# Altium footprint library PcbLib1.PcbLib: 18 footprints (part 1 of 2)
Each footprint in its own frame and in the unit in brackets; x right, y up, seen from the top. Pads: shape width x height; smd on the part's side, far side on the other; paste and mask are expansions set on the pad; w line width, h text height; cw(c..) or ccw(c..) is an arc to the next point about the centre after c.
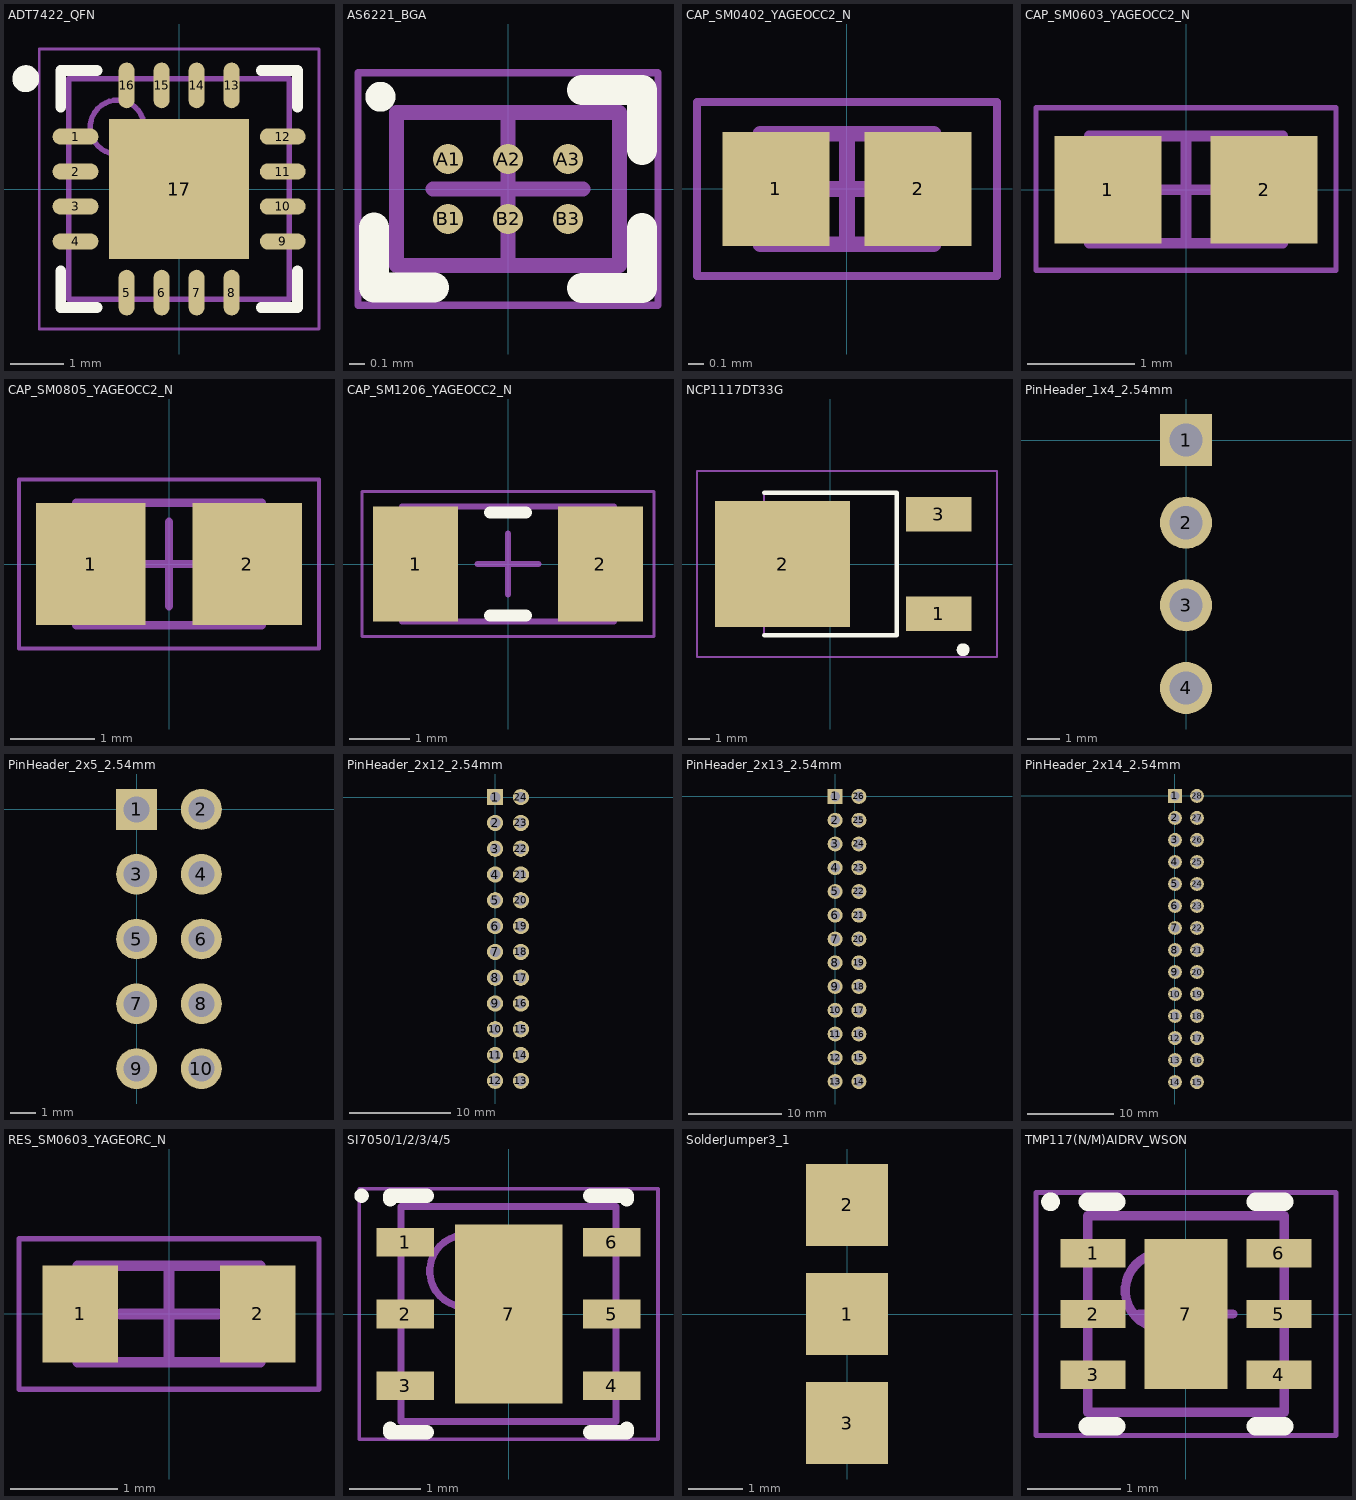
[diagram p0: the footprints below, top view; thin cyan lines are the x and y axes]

## ADT7422_QFN [mm] "QFN, 16-Leads, Body 4,00x4,00mm, Pitch 0,65mm, Thermal Pad 2,60x2,60mm, IPC Medium Density"
height 0.8
pads (17):
  oval 0.85x0.3 smd: 1(-1.925,0.975) 2(-1.925,0.325) 3(-1.925,-0.325) 4(-1.925,-0.975) 9(1.925,-0.975) 10(1.925,-0.325) 11(1.925,0.325) 12(1.925,0.975)
  oval 0.3x0.85 smd: 5(-0.975,-1.925) 6(-0.325,-1.925) 7(0.325,-1.925) 8(0.975,-1.925) 13(0.975,1.925) 14(0.325,1.925) 15(-0.325,1.925) 16(-0.975,1.925)
  rect 2.6x2.6 smd: 17(0,0)
Top Overlay:
  circle w0.25: c-2.85,2.05 r0.125
  lines w0.2: -2.2,-1.525 -2.2,-2.2 -1.525,-2.2 ; -2.2,1.525 -2.2,2.2 -1.525,2.2 ; 1.525,-2.2 2.2,-2.2 2.2,-1.525 ; 1.525,2.2 2.2,2.2 2.2,1.525
Top Courtyard:
  lines w0.05: -2.6,-2.6 -2.6,2.6 2.6,2.6 2.6,-2.6 -2.6,-2.6
  lines w0.1: -0.5,0 0.5,0 ; 0,-0.5 0,0.5
Mechanical 13:
  circle w0.1: c-1.15,1.15 r0.5
  lines w0.1: -2.05,-2.05 -2.05,2.05 2.05,2.05 2.05,-2.05 -2.05,-2.05
3D body: height 0.8, standoff 0.01, extent -2.05,-2.05 2.05,2.05

## AS6221_BGA [mm] "BGA, 6-Leads, Body 1,02x1,50mmx0,53mm, Pitch 0,40mm"
height 0.53
pads (6):
  round 0.2 smd: A1(-0.4,0.2) A2(0,0.2) A3(0.4,0.2) B1(-0.4,-0.2) B2(0,-0.2) B3(0.4,-0.2)
Top Overlay:
  circle w0.1: c-0.85,0.615 r0.05
  lines w0.2: -0.893,-0.256 -0.893,-0.656 -0.493,-0.656 ; 0.494,-0.66 0.894,-0.66 0.894,-0.26 ; 0.494,0.661 0.894,0.661 0.894,0.261
Top Courtyard:
  lines w0.05: -1,-0.775 -1,0.775 1,0.775 1,-0.775 -1,-0.775
  lines w0.1: -0.5,0 0.5,0 ; 0,-0.5 0,0.5
Mechanical 13:
  lines w0.1: -0.745,-0.51 -0.745,0.51 0.745,0.51 0.745,-0.51 -0.745,-0.51
3D body: height 0.55, standoff 0.18, extent -0.745,-0.51 0.745,0.51

## CAP_SM0402_YAGEOCC2_N [mm] "Capacitor, Yageo CC Class2, SM0402, IPC Medium Density"
height 0.9
pads (2):
  rect 0.68x0.72 smd: 1(-0.45,0) 2(0.45,0)
Mechanical 13:
  lines w0.1: -0.55,-0.35 -0.55,0.35 0.55,0.35 0.55,-0.35 -0.55,-0.35
Mechanical 15:
  lines w0.05: -0.95,-0.55 -0.95,0.55 0.95,0.55 0.95,-0.55 -0.95,-0.55
  lines w0.1: -0.35,0 0.35,0 ; 0,-0.35 0,0.35
3D body: height 0.6, standoff 0, extent -0.3,-0.35 0.3,0.35
3D body: height 0.6, standoff 0, extent -0.55,-0.35 -0.3,0.35
3D body: height 0.6, standoff 0, extent 0.3,-0.35 0.55,0.35

## CAP_SM0603_YAGEOCC2_N [mm] "Capacitor, Yageo CC Class2, SM0603, IPC Medium Density"
height 0.9
pads (2):
  rect 1x1 smd: 1(-0.727,0) 2(0.727,0)
Mechanical 13:
  lines w0.1: -0.9,-0.5 0.9,-0.5 0.9,0.5 -0.9,0.5 -0.9,-0.5
Mechanical 15:
  lines w0.05: -1.397,-0.75 1.397,-0.75 1.397,0.762 -1.397,0.762 -1.397,-0.75
  lines w0.1: -0.5,0 0.5,0 ; 0,-0.5 0,0.5
3D body: height 0.9, standoff 0, extent 0.5,-0.5 0.9,0.5
3D body: height 0.9, standoff 0, extent -0.9,-0.5 -0.5,0.5
3D body: height 0.9, standoff 0, extent -0.5,-0.5 0.5,0.5

## CAP_SM0805_YAGEOCC2_N [mm] "Capacitor, Yageo CC Class2, SM0805, IPC Medium Density"
height 1.45
pads (2):
  rect 1.3x1.45 smd: 1(-0.927,0) 2(0.927,0)
Mechanical 13:
  lines w0.1: -1.1,-0.725 -1.1,0.725 1.1,0.725 1.1,-0.725 -1.1,-0.725
Mechanical 15:
  lines w0.05: -1.778,-1 -1.778,1 1.778,1 1.778,-1 -1.778,-1
  lines w0.1: -0.5,0 0.5,0 ; 0,-0.5 0,0.5
3D body: height 1.45, standoff 0, extent -0.6,-0.725 0.6,0.725
3D body: height 1.45, standoff 0, extent -1.1,-0.725 -0.6,0.725
3D body: height 1.45, standoff 0, extent 0.6,-0.725 1.1,0.725

## CAP_SM1206_YAGEOCC2_N [mm] "Capacitor, Yageo CC Class2, SM1206, IPC Medium Density"
height 1.8
pads (2):
  rect 1.4x1.9 smd: 1(-1.527,0) 2(1.527,0)
Top Overlay:
  lines w0.2: -0.3,-0.85 0.3,-0.85 ; -0.3,0.85 0.3,0.85
Mechanical 13:
  lines w0.1: -1.75,-0.95 -1.75,0.95 1.75,0.95 1.75,-0.95 -1.75,-0.95
Mechanical 15:
  lines w0.05: -2.413,-1.2 -2.413,1.2 2.413,1.2 2.413,-1.2 -2.413,-1.2
  lines w0.1: -0.5,0 0.5,0 ; 0,-0.5 0,0.5
3D body: height 1.8, standoff 0, extent -1.25,-0.95 1.25,0.95
3D body: height 1.8, standoff 0, extent -1.75,-0.95 -1.25,0.95
3D body: height 1.8, standoff 0, extent 1.25,-0.95 1.75,0.95

## NCP1117DT33G [mm]
pads (3):
  rect 3x1.6 smd: 1(4.982,-2.285) 3(4.982,2.285)
  rect 6.2x5.8 smd: 2(-2.198,0)
Top Overlay:
  lines w0.2: -3.047,-3.27 3.048,-3.27 3.048,3.27 -3.047,3.27 ; 6.096,-3.741 ccw(c6.096,-3.937) 6.146,-3.747 ; 6.084,-3.936 cw(c6.134,-3.936) 6.184,-3.936 cw(c6.134,-3.936) 6.084,-3.936
Mechanical 15:
  lines w0.1: -3.047,-3.27 -3.047,3.27 3.048,3.27 3.048,-3.27 -3.047,-3.27
Mechanical 20:
  lines w0.1: -6.128,-4.27 -6.128,4.27 7.652,4.27 7.652,-4.27 -6.128,-4.27
3D body "NCP1117DT33G.stp": height 2.69, standoff -0.02, extent -4.678,-3.335 5.74,3.395

## PinHeader_1x4_2.54mm [mm]
pads (4):
  rect 1.6x1.6 hole 1.02: 1(0,0)
  round 1.6 hole 1.02: 2(0,-2.54) 3(0,-5.08) 4(0,-7.62)

## PinHeader_2x5_2.54mm [mm]
pads (10):
  rect 1.6x1.6 hole 1.02: 1(0,0)
  round 1.6 hole 1.02: 2(2.54,0) 3(0,-2.54) 4(2.54,-2.54) 5(0,-5.08) 6(2.54,-5.08) 7(0,-7.62) 8(2.54,-7.62) 9(0,-10.16) 10(2.54,-10.16)

## PinHeader_2x12_2.54mm [mm]
pads (24):
  rect 1.6x1.6 hole 1.02: 1(0,0)
  round 1.6 hole 1.02: 2(0,-2.54) 3(0,-5.08) 4(0,-7.62) 5(0,-10.16) 6(0,-12.7) 7(0,-15.24) 8(0,-17.78) 9(0,-20.32) 10(0,-22.86) 11(0,-25.4) 12(0,-27.94) 13(2.54,-27.94) 14(2.54,-25.4) 15(2.54,-22.86) 16(2.54,-20.32) 17(2.54,-17.78) 18(2.54,-15.24) 19(2.54,-12.7) 20(2.54,-10.16) 21(2.54,-7.62) 22(2.54,-5.08) 23(2.54,-2.54) 24(2.54,0)

## PinHeader_2x13_2.54mm [mm]
pads (26):
  rect 1.6x1.6 hole 1.02: 1(0,0)
  round 1.6 hole 1.02: 2(0,-2.54) 3(0,-5.08) 4(0,-7.62) 5(0,-10.16) 6(0,-12.7) 7(0,-15.24) 8(0,-17.78) 9(0,-20.32) 10(0,-22.86) 11(0,-25.4) 12(0,-27.94) 13(0,-30.48) 14(2.54,-30.48) 15(2.54,-27.94) 16(2.54,-25.4) 17(2.54,-22.86) 18(2.54,-20.32) 19(2.54,-17.78) 20(2.54,-15.24) 21(2.54,-12.7) 22(2.54,-10.16) 23(2.54,-7.62) 24(2.54,-5.08) 25(2.54,-2.54) 26(2.54,0)

## PinHeader_2x14_2.54mm [mm]
pads (28):
  rect 1.6x1.6 hole 1.02: 1(0,0)
  round 1.6 hole 1.02: 2(0,-2.54) 3(0,-5.08) 4(0,-7.62) 5(0,-10.16) 6(0,-12.7) 7(0,-15.24) 8(0,-17.78) 9(0,-20.32) 10(0,-22.86) 11(0,-25.4) 12(0,-27.94) 13(0,-30.48) 14(0,-33.02) 15(2.54,-33.02) 16(2.54,-30.48) 17(2.54,-27.94) 18(2.54,-25.4) 19(2.54,-22.86) 20(2.54,-20.32) 21(2.54,-17.78) 22(2.54,-15.24) 23(2.54,-12.7) 24(2.54,-10.16) 25(2.54,-7.62) 26(2.54,-5.08) 27(2.54,-2.54) 28(2.54,0)

## RES_SM0603_YAGEORC_N [mm] "Resistor, Yageo RC_L, SM0603, IPC Medium Density"
height 0.55
pads (2):
  rect 0.7x0.9 smd: 1(-0.827,0) 2(0.827,0)
Mechanical 13:
  lines w0.1: -0.85,-0.45 -0.85,0.45 0.85,0.45 0.85,-0.45 -0.85,-0.45
Mechanical 15:
  lines w0.05: -1.397,-0.7 -1.397,0.7 1.397,0.7 1.397,-0.7 -1.397,-0.7
  lines w0.1: -0.45,0 0.45,0 ; 0,-0.45 0,0.45
3D body: height 0.55, standoff 0, extent -0.6,-0.45 0.6,0.45
3D body: height 0.55, standoff 0, extent -0.85,-0.45 -0.6,0.45
3D body: height 0.55, standoff 0, extent 0.6,-0.45 0.85,0.45

## SI7050/1/2/3/4/5 [mm] "SON, 6-Leads, Body 3,00x3,00mm, Pitch 1,00mm, Thermal Pad 2,50x1,50mm, IPC Medium Density"
height 0.8
pads (7):
  rect 0.8x0.4 smd: 1(-1.44,1) 2(-1.44,0) 3(-1.44,-1) 4(1.44,-1) 5(1.44,0) 6(1.44,1)
  rect 1.5x2.5 smd: 7(0,0)
Top Overlay:
  circle w0.1: c-2.05,1.65 r0.05
  lines w0.2: -1.65,-1.6 -1.65,-1.65 -1.14,-1.65 ; -1.65,1.6 -1.65,1.65 -1.14,1.65 ; 1.14,-1.65 1.65,-1.65 1.65,-1.6 ; 1.14,1.65 1.65,1.65 1.65,1.6
Top Courtyard:
  lines w0.05: -2.085,-1.75 2.085,-1.75 2.085,1.75 -2.085,1.75 -2.085,-1.75
  lines w0.1: -0.5,0 0.5,0 ; 0,-0.5 0,0.5
Mechanical 13:
  circle w0.1: c-0.6,0.6 r0.5
  lines w0.1: -1.5,-1.5 1.5,-1.5 1.5,1.5 -1.5,1.5 -1.5,-1.5
3D body: height 0.8, standoff 0, extent -1.5,-1.5 1.5,1.5

## SolderJumper3_1 [mm]
pads (3):
  rect 1.5x1.5 smd: 1(0,0) 2(0,2) 3(0,-2)

## TMP117(N/M)AIDRV_WSON [mm] "SON127P600-8N"
height 0.8
pads (7):
  rect 0.7x0.3 smd: 1(-0.995,0.65) 2(-0.995,0) 3(-0.995,-0.65) 4(0.995,-0.65) 5(0.995,0) 6(0.995,0.65)
  rect 0.89x1.6 smd: 7(0,0)
Top Overlay:
  circle w0.1: c-1.45,1.2 r0.05
  lines w0.2: -1.05,-1.2 -0.745,-1.2 ; -1.05,1.2 -0.745,1.2 ; 0.745,-1.2 1.05,-1.2 ; 0.745,1.2 1.05,1.2
Top Courtyard:
  lines w0.05: -1.605,-1.3 1.605,-1.3 1.605,1.3 -1.605,1.3 -1.605,-1.3
  lines w0.1: -0.5,0 0.5,0 ; 0,-0.5 0,0.5
Mechanical 13:
  circle w0.1: c-0.25,0.25 r0.4
  lines w0.1: -1.05,-1.05 1.05,-1.05 1.05,1.05 -1.05,1.05 -1.05,-1.05
3D body: height 0.8, standoff 0, extent -1.05,-1.05 1.05,1.05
